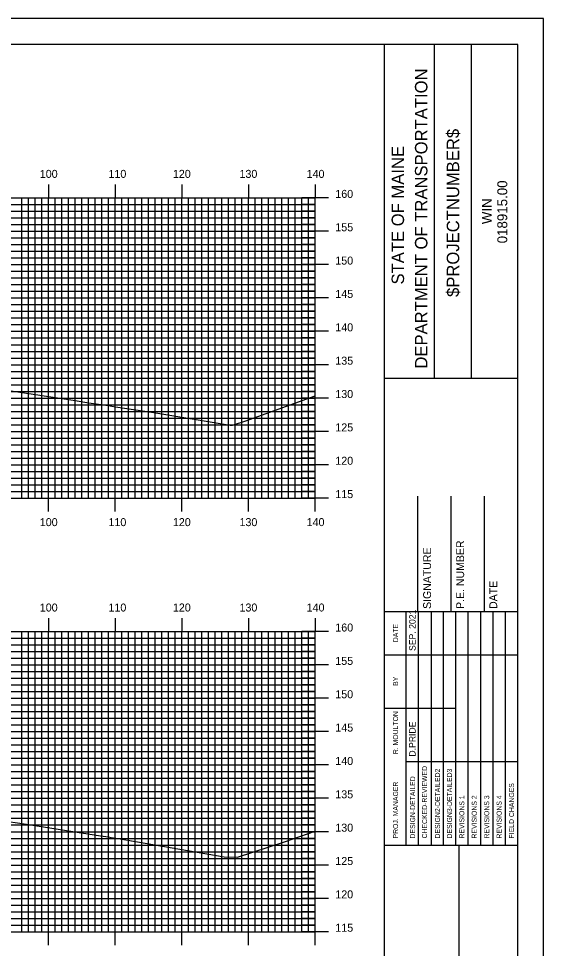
# Model space of a CAD drawing. Extents: x 851139 to 851482, y 366605 to 366825.
# Drawn here: x 851400.4 to 851479.2, y 366685.6 to 366824.9 of the extents above; entities that cross this region are included whole.
import ezdxf

# ---------------------------------------------------------------- set-up
doc = ezdxf.new("R2010")
doc.units = 0
for name, color, linetype in [('BORDER', 7, 'Continuous'), ('H_V ANNOTATION', 7, 'Continuous'), ('MAJOR', 7, 'Continuous'), ('MINOR', 7, 'Continuous'), ('PLOT BOUNDARY', 7, 'Continuous'), ('S_Roadway_Centerline', 7, 'Continuous')]:
    doc.layers.add(name, color=color, linetype=linetype)

msp = doc.modelspace()

# ---------------------------------------------------------------- linework, layer by layer
at = {"layer": 'BORDER'}
for p, q in [((851455.34, 366611.06), (851455.34, 366821.06)), ((851462.8, 366771.05), (851462.8, 366821.05)), ((851468.39, 366771.05), (851468.39, 366821.05)), ((851455.34, 366771.04), (851475.34, 366771.04)), ((851460.34, 366736.06), (851460.34, 366753.36)), ((851465.34, 366736.06), (851465.34, 366753.36)), ((851470.34, 366736.06), (851470.34, 366753.36)), ((851455.34, 366736.06), (851475.34, 366736.06)), ((851455.34, 366701.06), (851475.34, 366701.06)), ((851466.52, 366631.06), (851466.52, 366701.06))]:
    msp.add_line(p, q, dxfattribs=at)
msp.add_lwpolyline([(851155.34, 366611.06), (851475.34, 366611.06), (851475.34, 366821.06), (851155.34, 366821.06)], close=True, dxfattribs=at)
for points in [[(851458.57, 366729.56), (851458.57, 366736.06)], [(851460.43, 366701.07), (851460.43, 366736.06)], [(851462.3, 366736.06), (851462.3, 366701.07)], [(851464.16, 366701.07), (851464.16, 366736.06)], [(851466.02, 366701.07), (851466.02, 366736.06)], [(851467.89, 366701.07), (851467.89, 366736.06)], [(851469.75, 366701.07), (851469.75, 366736.06)], [(851471.61, 366701.07), (851471.61, 366736.06)], [(851473.48, 366701.07), (851473.48, 366736.06)], [(851458.57, 366701.07), (851458.57, 366734.65)], [(851455.34, 366729.56), (851475.34, 366729.56)], [(851455.34, 366721.56), (851458.57, 366721.56)], [(851458.57, 366721.56), (851466.02, 366721.56)], [(851458.57, 366713.56), (851475.34, 366713.56)]]:
    msp.add_lwpolyline(points, dxfattribs=at)
at = {"layer": 'MAJOR'}
for p, q in [((851404.94, 366800.06), (851404.94, 366798.06)), ((851414.94, 366800.06), (851414.94, 366798.06)), ((851424.94, 366800.06), (851424.94, 366798.06)), ((851434.94, 366800.06), (851434.94, 366798.06)), ((851444.94, 366800.06), (851444.94, 366798.06)), ((851164.94, 366798.06), (851444.94, 366798.06)), ((851164.94, 366798.06), (851444.94, 366798.06)), ((851404.94, 366753.06), (851404.94, 366798.06)), ((851414.94, 366753.06), (851414.94, 366798.06)), ((851424.94, 366753.06), (851424.94, 366798.06)), ((851434.94, 366753.06), (851434.94, 366798.06)), ((851446.94, 366798.06), (851442.93, 366798.06)), ((851444.94, 366753.06), (851444.94, 366798.06)), ((851444.94, 366753.06), (851444.94, 366798.06)), ((851164.94, 366793.06), (851444.94, 366793.06)), ((851446.94, 366793.06), (851442.93, 366793.06)), ((851164.94, 366788.06), (851444.94, 366788.06)), ((851446.94, 366788.06), (851442.93, 366788.06)), ((851164.94, 366783.06), (851444.94, 366783.06)), ((851446.94, 366783.06), (851442.93, 366783.06)), ((851164.94, 366778.06), (851444.94, 366778.06)), ((851446.94, 366778.06), (851442.93, 366778.06)), ((851164.94, 366773.06), (851444.94, 366773.06)), ((851446.94, 366773.06), (851442.93, 366773.06)), ((851164.94, 366768.06), (851444.94, 366768.06)), ((851446.94, 366768.06), (851442.93, 366768.06)), ((851164.94, 366763.06), (851444.94, 366763.06)), ((851446.94, 366763.06), (851442.93, 366763.06)), ((851164.94, 366758.06), (851444.94, 366758.06)), ((851446.94, 366758.06), (851442.93, 366758.06)), ((851164.94, 366753.06), (851444.94, 366753.06)), ((851164.94, 366753.06), (851444.94, 366753.06)), ((851404.94, 366751.05), (851404.94, 366753.06)), ((851414.94, 366751.05), (851414.94, 366753.06)), ((851424.94, 366751.05), (851424.94, 366753.06)), ((851434.94, 366751.05), (851434.94, 366753.06)), ((851446.94, 366753.06), (851442.93, 366753.06)), ((851444.94, 366751.05), (851444.94, 366753.06)), ((851404.94, 366735.06), (851404.94, 366733.06)), ((851414.94, 366735.06), (851414.94, 366733.06)), ((851424.94, 366735.06), (851424.94, 366733.06)), ((851434.94, 366735.06), (851434.94, 366733.06)), ((851444.94, 366735.06), (851444.94, 366733.06)), ((851164.94, 366733.06), (851444.94, 366733.06)), ((851164.94, 366733.06), (851444.94, 366733.06)), ((851404.94, 366688.06), (851404.94, 366733.06)), ((851414.94, 366688.06), (851414.94, 366733.06)), ((851424.94, 366688.06), (851424.94, 366733.06)), ((851434.94, 366688.06), (851434.94, 366733.06)), ((851446.94, 366733.06), (851442.93, 366733.06)), ((851444.94, 366688.06), (851444.94, 366733.06)), ((851444.94, 366688.06), (851444.94, 366733.06)), ((851164.94, 366728.06), (851444.94, 366728.06)), ((851446.94, 366728.06), (851442.93, 366728.06)), ((851164.94, 366723.06), (851444.94, 366723.06)), ((851446.94, 366723.06), (851442.93, 366723.06)), ((851164.94, 366718.06), (851444.94, 366718.06)), ((851446.94, 366718.06), (851442.93, 366718.06)), ((851164.94, 366713.06), (851444.94, 366713.06)), ((851446.94, 366713.06), (851442.93, 366713.06)), ((851164.94, 366708.06), (851444.94, 366708.06)), ((851446.94, 366708.06), (851442.93, 366708.06)), ((851164.94, 366703.06), (851444.94, 366703.06)), ((851446.94, 366703.06), (851442.93, 366703.06)), ((851164.94, 366698.06), (851444.94, 366698.06)), ((851446.94, 366698.06), (851442.93, 366698.06)), ((851164.94, 366693.06), (851444.94, 366693.06)), ((851446.94, 366693.06), (851442.93, 366693.06)), ((851164.94, 366688.06), (851444.94, 366688.06)), ((851164.94, 366688.06), (851444.94, 366688.06)), ((851404.94, 366686.05), (851404.94, 366688.06)), ((851414.94, 366686.05), (851414.94, 366688.06)), ((851424.94, 366686.05), (851424.94, 366688.06)), ((851434.94, 366686.05), (851434.94, 366688.06)), ((851446.94, 366688.06), (851442.93, 366688.06)), ((851444.94, 366686.05), (851444.94, 366688.06))]:
    msp.add_line(p, q, dxfattribs=at)
at = {"layer": 'MINOR'}
for p, q in [((851164.94, 366797.06), (851444.94, 366797.06)), ((851400.94, 366753.06), (851400.94, 366798.06)), ((851401.94, 366753.06), (851401.94, 366798.06)), ((851402.94, 366753.06), (851402.94, 366798.06)), ((851403.94, 366753.06), (851403.94, 366798.06)), ((851405.94, 366753.06), (851405.94, 366798.06)), ((851406.94, 366753.06), (851406.94, 366798.06)), ((851407.94, 366753.06), (851407.94, 366798.06)), ((851408.94, 366753.06), (851408.94, 366798.06)), ((851409.94, 366753.06), (851409.94, 366798.06)), ((851410.94, 366753.06), (851410.94, 366798.06)), ((851411.94, 366753.06), (851411.94, 366798.06)), ((851412.94, 366753.06), (851412.94, 366798.06)), ((851413.94, 366753.06), (851413.94, 366798.06)), ((851415.94, 366753.06), (851415.94, 366798.06)), ((851416.94, 366753.06), (851416.94, 366798.06)), ((851417.94, 366753.06), (851417.94, 366798.06)), ((851418.94, 366753.06), (851418.94, 366798.06)), ((851419.94, 366753.06), (851419.94, 366798.06)), ((851420.94, 366753.06), (851420.94, 366798.06)), ((851421.94, 366753.06), (851421.94, 366798.06)), ((851422.94, 366753.06), (851422.94, 366798.06)), ((851423.94, 366753.06), (851423.94, 366798.06)), ((851425.94, 366753.06), (851425.94, 366798.06)), ((851426.94, 366753.06), (851426.94, 366798.06)), ((851427.94, 366753.06), (851427.94, 366798.06)), ((851428.94, 366753.06), (851428.94, 366798.06)), ((851429.94, 366753.06), (851429.94, 366798.06)), ((851430.94, 366753.06), (851430.94, 366798.06)), ((851431.94, 366753.06), (851431.94, 366798.06)), ((851432.94, 366753.06), (851432.94, 366798.06)), ((851433.94, 366753.06), (851433.94, 366798.06)), ((851435.94, 366753.06), (851435.94, 366798.06)), ((851436.94, 366753.06), (851436.94, 366798.06)), ((851437.94, 366753.06), (851437.94, 366798.06)), ((851438.94, 366753.06), (851438.94, 366798.06)), ((851439.94, 366753.06), (851439.94, 366798.06)), ((851440.94, 366753.06), (851440.94, 366798.06)), ((851441.94, 366753.06), (851441.94, 366798.06)), ((851444.94, 366797.06), (851442.93, 366797.06)), ((851442.94, 366753.06), (851442.94, 366798.06)), ((851443.94, 366753.06), (851443.94, 366798.06)), ((851164.94, 366796.06), (851444.94, 366796.06)), ((851444.94, 366796.06), (851442.93, 366796.06)), ((851164.94, 366795.06), (851444.94, 366795.06)), ((851164.94, 366794.06), (851444.94, 366794.06)), ((851444.94, 366795.06), (851442.93, 366795.06)), ((851444.94, 366794.06), (851442.93, 366794.06)), ((851164.94, 366792.06), (851444.94, 366792.06)), ((851444.94, 366792.06), (851442.93, 366792.06)), ((851164.94, 366791.06), (851444.94, 366791.06)), ((851164.94, 366790.06), (851444.94, 366790.06)), ((851444.94, 366791.06), (851442.93, 366791.06)), ((851444.94, 366790.06), (851442.93, 366790.06)), ((851164.94, 366789.06), (851444.94, 366789.06)), ((851444.94, 366789.06), (851442.93, 366789.06)), ((851164.94, 366787.06), (851444.94, 366787.06)), ((851444.94, 366787.06), (851442.93, 366787.06)), ((851164.94, 366786.06), (851444.94, 366786.06)), ((851444.94, 366786.06), (851442.93, 366786.06)), ((851164.94, 366785.06), (851444.94, 366785.06)), ((851444.94, 366785.06), (851442.93, 366785.06)), ((851164.94, 366784.06), (851444.94, 366784.06)), ((851444.94, 366784.06), (851442.93, 366784.06)), ((851164.94, 366782.06), (851444.94, 366782.06)), ((851444.94, 366782.06), (851442.93, 366782.06)), ((851164.94, 366781.06), (851444.94, 366781.06)), ((851164.94, 366780.06), (851444.94, 366780.06)), ((851444.94, 366781.06), (851442.93, 366781.06)), ((851444.94, 366780.06), (851442.93, 366780.06)), ((851164.94, 366779.06), (851444.94, 366779.06)), ((851444.94, 366779.06), (851442.93, 366779.06)), ((851164.94, 366777.06), (851444.94, 366777.06)), ((851164.94, 366776.06), (851444.94, 366776.06)), ((851444.94, 366777.06), (851442.93, 366777.06)), ((851444.94, 366776.06), (851442.93, 366776.06)), ((851164.94, 366775.06), (851444.94, 366775.06)), ((851444.94, 366775.06), (851442.93, 366775.06)), ((851164.94, 366774.06), (851444.94, 366774.06)), ((851444.94, 366774.06), (851442.93, 366774.06)), ((851164.94, 366772.06), (851444.94, 366772.06)), ((851444.94, 366772.06), (851442.93, 366772.06)), ((851164.94, 366771.06), (851444.94, 366771.06)), ((851444.94, 366771.06), (851442.93, 366771.06)), ((851164.94, 366770.06), (851444.94, 366770.06)), ((851164.94, 366769.06), (851444.94, 366769.06)), ((851444.94, 366770.06), (851442.93, 366770.06)), ((851444.94, 366769.06), (851442.93, 366769.06)), ((851164.94, 366767.06), (851444.94, 366767.06)), ((851444.94, 366767.06), (851442.93, 366767.06)), ((851164.94, 366766.06), (851444.94, 366766.06)), ((851164.94, 366765.06), (851444.94, 366765.06)), ((851444.94, 366766.06), (851442.93, 366766.06)), ((851444.94, 366765.06), (851442.93, 366765.06)), ((851164.94, 366764.06), (851444.94, 366764.06)), ((851444.94, 366764.06), (851442.93, 366764.06)), ((851164.94, 366762.06), (851444.94, 366762.06)), ((851444.94, 366762.06), (851442.93, 366762.06)), ((851164.94, 366761.06), (851444.94, 366761.06)), ((851444.94, 366761.06), (851442.93, 366761.06)), ((851164.94, 366760.06), (851444.94, 366760.06)), ((851444.94, 366760.06), (851442.93, 366760.06)), ((851164.94, 366759.06), (851444.94, 366759.06)), ((851444.94, 366759.06), (851442.93, 366759.06)), ((851164.94, 366757.06), (851444.94, 366757.06)), ((851444.94, 366757.06), (851442.93, 366757.06)), ((851164.94, 366756.06), (851444.94, 366756.06)), ((851164.94, 366755.06), (851444.94, 366755.06)), ((851444.94, 366756.06), (851442.93, 366756.06)), ((851444.94, 366755.06), (851442.93, 366755.06)), ((851164.94, 366754.06), (851444.94, 366754.06)), ((851444.94, 366754.06), (851442.93, 366754.06)), ((851400.94, 366688.06), (851400.94, 366733.06)), ((851401.94, 366688.06), (851401.94, 366733.06)), ((851402.94, 366688.06), (851402.94, 366733.06)), ((851403.94, 366688.06), (851403.94, 366733.06)), ((851405.94, 366688.06), (851405.94, 366733.06)), ((851406.94, 366688.06), (851406.94, 366733.06)), ((851407.94, 366688.06), (851407.94, 366733.06)), ((851408.94, 366688.06), (851408.94, 366733.06)), ((851409.94, 366688.06), (851409.94, 366733.06)), ((851410.94, 366688.06), (851410.94, 366733.06)), ((851411.94, 366688.06), (851411.94, 366733.06)), ((851412.94, 366688.06), (851412.94, 366733.06)), ((851413.94, 366688.06), (851413.94, 366733.06)), ((851415.94, 366688.06), (851415.94, 366733.06)), ((851416.94, 366688.06), (851416.94, 366733.06)), ((851417.94, 366688.06), (851417.94, 366733.06)), ((851418.94, 366688.06), (851418.94, 366733.06)), ((851419.94, 366688.06), (851419.94, 366733.06)), ((851420.94, 366688.06), (851420.94, 366733.06)), ((851421.94, 366688.06), (851421.94, 366733.06)), ((851422.94, 366688.06), (851422.94, 366733.06)), ((851423.94, 366688.06), (851423.94, 366733.06)), ((851425.94, 366688.06), (851425.94, 366733.06)), ((851426.94, 366688.06), (851426.94, 366733.06)), ((851427.94, 366688.06), (851427.94, 366733.06)), ((851428.94, 366688.06), (851428.94, 366733.06)), ((851429.94, 366688.06), (851429.94, 366733.06)), ((851430.94, 366688.06), (851430.94, 366733.06)), ((851431.94, 366688.06), (851431.94, 366733.06)), ((851432.94, 366688.06), (851432.94, 366733.06)), ((851433.94, 366688.06), (851433.94, 366733.06)), ((851435.94, 366688.06), (851435.94, 366733.06)), ((851436.94, 366688.06), (851436.94, 366733.06)), ((851437.94, 366688.06), (851437.94, 366733.06)), ((851438.94, 366688.06), (851438.94, 366733.06)), ((851439.94, 366688.06), (851439.94, 366733.06)), ((851440.94, 366688.06), (851440.94, 366733.06)), ((851441.94, 366688.06), (851441.94, 366733.06)), ((851442.94, 366688.06), (851442.94, 366733.06)), ((851443.94, 366688.06), (851443.94, 366733.06)), ((851164.94, 366732.06), (851444.94, 366732.06)), ((851444.94, 366732.06), (851442.93, 366732.06)), ((851164.94, 366731.06), (851444.94, 366731.06)), ((851164.94, 366730.06), (851444.94, 366730.06)), ((851444.94, 366731.06), (851442.93, 366731.06)), ((851444.94, 366730.06), (851442.93, 366730.06)), ((851164.94, 366729.06), (851444.94, 366729.06)), ((851444.94, 366729.06), (851442.93, 366729.06)), ((851164.94, 366727.06), (851444.94, 366727.06)), ((851164.94, 366726.06), (851444.94, 366726.06)), ((851444.94, 366727.06), (851442.93, 366727.06)), ((851444.94, 366726.06), (851442.93, 366726.06)), ((851164.94, 366725.06), (851444.94, 366725.06)), ((851444.94, 366725.06), (851442.93, 366725.06)), ((851164.94, 366724.06), (851444.94, 366724.06)), ((851444.94, 366724.06), (851442.93, 366724.06)), ((851164.94, 366722.06), (851444.94, 366722.06)), ((851444.94, 366722.06), (851442.93, 366722.06)), ((851164.94, 366721.06), (851444.94, 366721.06)), ((851444.94, 366721.06), (851442.93, 366721.06)), ((851164.94, 366720.06), (851444.94, 366720.06)), ((851164.94, 366719.06), (851444.94, 366719.06)), ((851444.94, 366720.06), (851442.93, 366720.06)), ((851444.94, 366719.06), (851442.93, 366719.06)), ((851164.94, 366717.06), (851444.94, 366717.06)), ((851164.94, 366716.06), (851444.94, 366716.06)), ((851444.94, 366717.06), (851442.93, 366717.06)), ((851444.94, 366716.06), (851442.93, 366716.06)), ((851164.94, 366715.06), (851444.94, 366715.06)), ((851444.94, 366715.06), (851442.93, 366715.06)), ((851164.94, 366714.06), (851444.94, 366714.06)), ((851444.94, 366714.06), (851442.93, 366714.06)), ((851164.94, 366712.06), (851444.94, 366712.06)), ((851444.94, 366712.06), (851442.93, 366712.06)), ((851164.94, 366711.06), (851444.94, 366711.06)), ((851444.94, 366711.06), (851442.93, 366711.06)), ((851164.94, 366710.06), (851444.94, 366710.06)), ((851164.94, 366709.06), (851444.94, 366709.06)), ((851444.94, 366710.06), (851442.93, 366710.06)), ((851444.94, 366709.06), (851442.93, 366709.06)), ((851164.94, 366707.06), (851444.94, 366707.06)), ((851444.94, 366707.06), (851442.93, 366707.06)), ((851164.94, 366706.06), (851444.94, 366706.06)), ((851164.94, 366705.06), (851444.94, 366705.06)), ((851444.94, 366706.06), (851442.93, 366706.06)), ((851444.94, 366705.06), (851442.93, 366705.06)), ((851164.94, 366704.06), (851444.94, 366704.06)), ((851444.94, 366704.06), (851442.93, 366704.06)), ((851164.94, 366702.06), (851444.94, 366702.06)), ((851444.94, 366702.06), (851442.93, 366702.06)), ((851164.94, 366701.06), (851444.94, 366701.06)), ((851444.94, 366701.06), (851442.93, 366701.06)), ((851164.94, 366700.06), (851444.94, 366700.06)), ((851444.94, 366700.06), (851442.93, 366700.06)), ((851164.94, 366699.06), (851444.94, 366699.06)), ((851444.94, 366699.06), (851442.93, 366699.06)), ((851164.94, 366697.06), (851444.94, 366697.06)), ((851444.94, 366697.06), (851442.93, 366697.06)), ((851164.94, 366696.06), (851444.94, 366696.06)), ((851164.94, 366695.06), (851444.94, 366695.06)), ((851444.94, 366696.06), (851442.93, 366696.06)), ((851444.94, 366695.06), (851442.93, 366695.06)), ((851164.94, 366694.06), (851444.94, 366694.06)), ((851444.94, 366694.06), (851442.93, 366694.06)), ((851164.94, 366692.06), (851444.94, 366692.06)), ((851164.94, 366691.06), (851444.94, 366691.06)), ((851444.94, 366692.06), (851442.93, 366692.06)), ((851444.94, 366691.06), (851442.93, 366691.06)), ((851164.94, 366690.06), (851444.94, 366690.06)), ((851444.94, 366690.06), (851442.93, 366690.06)), ((851164.94, 366689.06), (851444.94, 366689.06)), ((851444.94, 366689.06), (851442.93, 366689.06))]:
    msp.add_line(p, q, dxfattribs=at)
at = {"layer": 'PLOT BOUNDARY'}
msp.add_lwpolyline([(851139.15, 366604.94), (851479.15, 366604.94), (851479.15, 366824.94), (851139.15, 366824.94)], close=True, dxfattribs=at)
at = {"layer": 'S_Roadway_Centerline'}
for points in [[(851398.99, 366769.19), (851408.62, 366767.73), (851410.95, 366767.36), (851413.88, 366766.93), (851414.98, 366766.75), (851420.73, 366765.87), (851432.19, 366763.97), (851432.51, 366764.01), (851434.52, 366764.65), (851444.94, 366768.4)], [(851398.12, 366704.67), (851400.99, 366704.27), (851412.72, 366702.45), (851413.94, 366702.27), (851414.34, 366702.2), (851415.39, 366702.04), (851431.29, 366699.29), (851433.26, 366699.22), (851440.33, 366701.54), (851444.94, 366703.15)]]:
    msp.add_lwpolyline(points, dxfattribs=at)

# ---------------------------------------------------------------- texts
at = {"layer": 'BORDER'}
for s, height, p in [('DEPARTMENT OF TRANSPORTATION', 1.8635, (851461.75, 366772.47)), ('$PROJECTNUMBER$', 1.8635, (851466.52, 366783.21)), ('STATE OF MAINE', 1.8635, (851458.25, 366785.08)), ('018915.00', 1.491, (851473.73, 366791.25)), ('WIN', 1.491, (851471.41, 366794.12)), ('P.E. NUMBER', 1.1811, (851467.26, 366736.45)), ('SIGNATURE', 1.181, (851462.3, 366736.45)), ('DATE', 1.181, (851472.22, 366736.45)), ('SEP. 2021', 0.969, (851459.98, 366730.15)), ('DATE', 0.743, (851457.35, 366731.47)), ('BY', 0.743, (851457.35, 366724.93)), ('R. MOULTON', 0.745, (851457.35, 366714.67)), ('D.PRIDE', 0.969, (851459.98, 366714.31)), ('CHECKED-REVIEWED', 0.7455, (851461.7, 366702.04)), ('DESIGN2-DETAILED2', 0.7455, (851463.64, 366702.04)), ('DESIGN3-DETAILED3', 0.7455, (851465.43, 366702.04)), ('DESIGN-DETAILED', 0.7455, (851459.91, 366702.04)), ('PROJ. MANAGER', 0.7455, (851457.35, 366702.04)), ('FIELD CHANGES', 0.7455, (851474.74, 366702.04)), ('REVISIONS 1', 0.7455, (851467.29, 366702.04)), ('REVISIONS 2', 0.7455, (851469.15, 366702.04)), ('REVISIONS 3', 0.7455, (851471.02, 366702.04)), ('REVISIONS 4', 0.7455, (851472.88, 366702.04))]:
    msp.add_text(s, height=height, rotation=90, dxfattribs=at).set_placement(p)
at = {"layer": 'H_V ANNOTATION'}
for s, p in [('100', (851403.62, 366801.06)), ('110', (851413.92, 366801.06)), ('120', (851423.58, 366801.06)), ('130', (851433.57, 366801.06)), ('140', (851443.64, 366801.06)), ('160', (851447.94, 366798.06)), ('155', (851447.94, 366793.06)), ('150', (851447.94, 366788.06)), ('145', (851447.94, 366783.06)), ('140', (851447.94, 366778.06)), ('135', (851447.94, 366773.06)), ('130', (851447.94, 366768.06)), ('125', (851447.94, 366763.06)), ('120', (851447.94, 366758.06)), ('115', (851447.94, 366753.06)), ('100', (851403.62, 366748.86)), ('110', (851413.92, 366748.86)), ('120', (851423.58, 366748.86)), ('130', (851433.57, 366748.86)), ('140', (851443.64, 366748.86)), ('100', (851403.62, 366736.06)), ('110', (851413.92, 366736.06)), ('120', (851423.58, 366736.06)), ('130', (851433.57, 366736.06)), ('140', (851443.64, 366736.06)), ('160', (851447.94, 366733.06)), ('155', (851447.94, 366728.06)), ('150', (851447.94, 366723.06)), ('145', (851447.94, 366718.06)), ('140', (851447.94, 366713.06)), ('135', (851447.94, 366708.06)), ('130', (851447.94, 366703.06)), ('125', (851447.94, 366698.06)), ('120', (851447.94, 366693.06)), ('115', (851447.94, 366688.06))]:
    msp.add_text(s, height=1.2, dxfattribs=at).set_placement(p)

doc.saveas('drawing.dxf')
